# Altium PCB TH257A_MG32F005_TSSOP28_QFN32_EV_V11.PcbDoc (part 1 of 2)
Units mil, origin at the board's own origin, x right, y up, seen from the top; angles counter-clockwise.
Board outline 4094.49 x 2637.8 mil, 2 copper layers (Top Layer, Bottom Layer); 102 components, 87 nets, 480 pads, 216 vias.
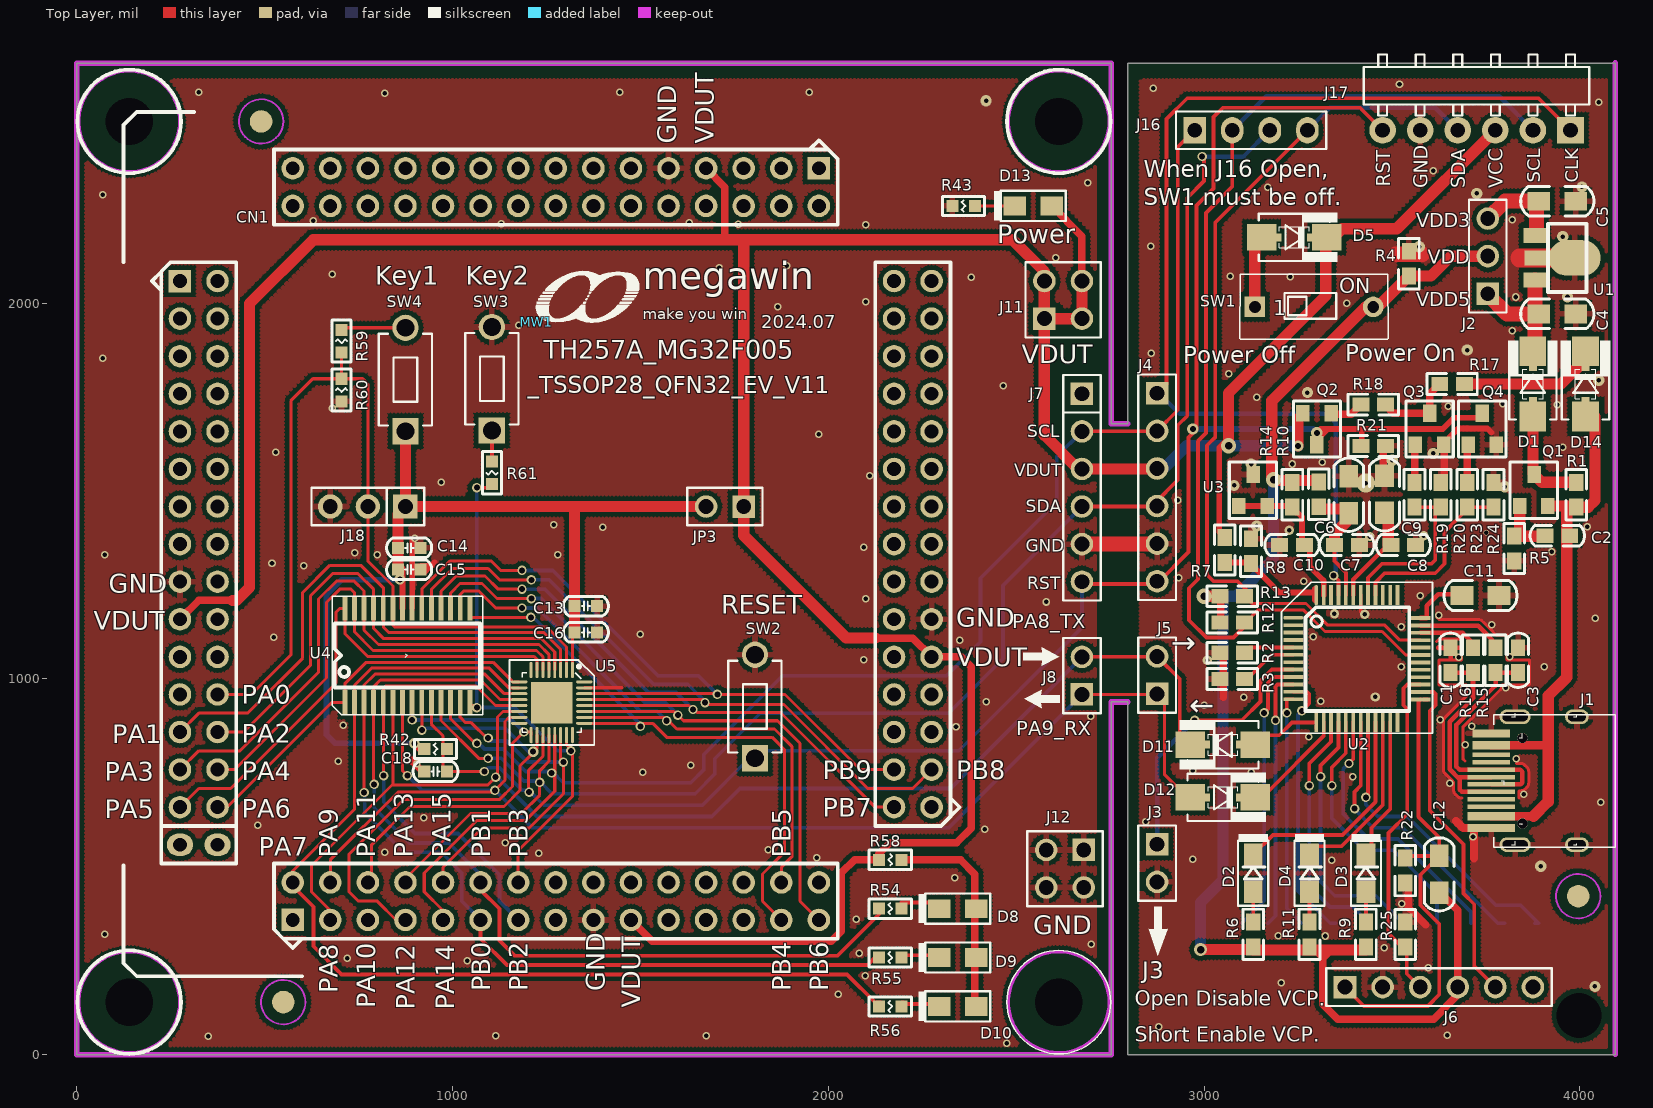
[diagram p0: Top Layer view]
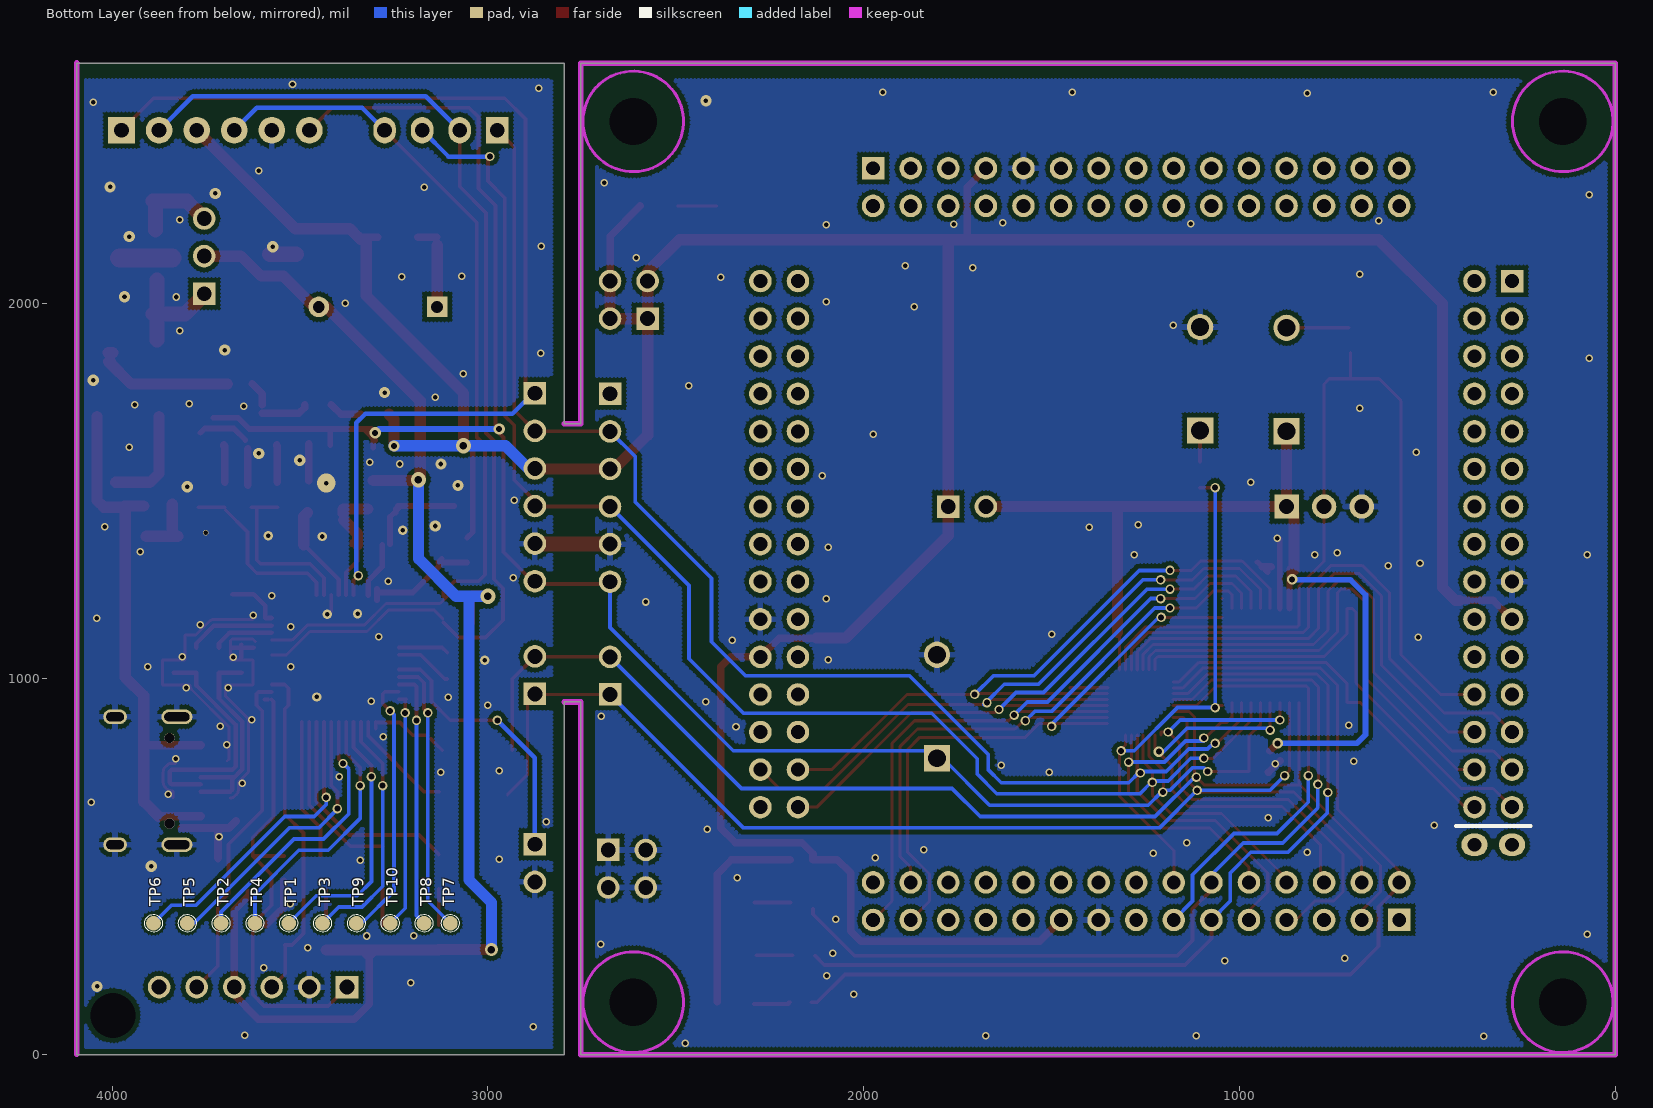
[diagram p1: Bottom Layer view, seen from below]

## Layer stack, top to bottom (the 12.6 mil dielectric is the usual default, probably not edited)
Top Layer: signal copper 1.4
Dielectric: dielectric 12.6, FR-4, Dk 4.8
Bottom Layer: signal copper 1.4

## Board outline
0,0 0,2637.8 2753.39,2637.8 2753.39,1678.74 2796.69,1678.74 2796.69,2637.8 4094.49,2637.8 4094.49,0 2796.69,0 2796.69,938.74 2753.39,938.74 2753.39,0

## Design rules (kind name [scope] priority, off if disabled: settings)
Clearance 12 [All] p1 off: gap=12
Clearance 7 [All] p2 off: gap=7
Clearance 6 [All] p3: gap=6
HoleSize 500-HoleSize [All] p1: absolutevalues=TRUE maxlimit=1500 minlimit=1 maxpercent=80.000 minpercent=20.000
PolygonConnect VIA [ISVIA] p1: connectstyle=Direct reliefconductorwidth=10 reliefentries=4 polygonreliefangle="90 Angle"
PolygonConnect "15 PolygonConnect" [All] p2: connectstyle=Relief reliefconductorwidth=15 reliefentries=4 polygonreliefangle="90 Angle"
RoomDefinition 3_MG32F005_QFN32 [InComponentClass('3_MG32F005_QFN32')] p1: confinementstyle=ConfineIn formatcopy=TRUE lockcomponents=FALSE outline 60.04,-466.26 4130,-466.26 4130,2953.74 60.04,2953.74
RoomDefinition 2_MG32F005_TSSOP28 [InComponentClass('2_MG32F005_TSSOP28')] p2: confinementstyle=ConfineIn formatcopy=TRUE lockcomponents=FALSE outline -190,-175 4240.04,-175 4240.04,2710 -190,2710
RoomDefinition 1_MLink_V13 [InComponentClass('1_MLink_V13')] p3: confinementstyle=ConfineIn formatcopy=TRUE lockcomponents=FALSE outline -110,-220 4180,-220 4180,2775 -110,2775
RoutingVias [All] p1: holewidth=16 width=25 viastyle="Through Hole" minholewidth=12 minwidth=25 maxholewidth=28 maxwidth=50
ShortCircuit [All] p1 off: allowed=FALSE
SilkscreenOverComponentPads [All] p1: minsilkscreentomaskgap=10
SolderMaskExpansion [All] p1: expansion=4
UnRoutedNet [All] p1 off:
Width [All] p1: maxlimit=100 minlimit=6 preferedwidth=8
24 further rules are at their usual default settings.

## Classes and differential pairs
component class 2_MG32F005_TSSOP28: C14 C15 C18 CN1 D8 D9 D10 D13 J7 J8 J11 J12 J18 JP3 R42 R43 R54 R55 R56 R58 R59 R60 R61 SW2 SW3 SW4 U4
component class 1_MLink_V13: C1 C2 C3 C4 C5 C6 C7 C8 C9 C10 C11 C12 D1 D2 D3 D4 D5 D11 D12 D14 J1 J2 J3 J4 J5 J6 J16 J17 MW1 Q1 Q2 Q3 Q4 R1 R2 R3 R4 R5 R6 R7 R8 R9 R10 R11 R12 R13 R14 R15 R16 R17 R18 R19 R20 R21 R22 R23 R24 R25 SW1 TP1 TP2 TP3 TP4 TP5 TP6 TP7 TP8 TP9 TP10 U1 U2 U3
component class 3_MG32F005_QFN32: C13 C16 U5

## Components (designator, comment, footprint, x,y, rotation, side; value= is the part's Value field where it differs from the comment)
C1 "15pF" 0603C 3655.59,1050 r270 top
C2 "0.1uF" 0603C 3940,1381.26 r0 top
C3 "15pF" 0603C 3835.59,1050 r270 top
C4 "4.7uF" 0805C 3940,1971.26 r0 top
C5 "4.7uF" 0805C 3940,2271.26 r0 top
C6 "4.7uF" 0805C 3385,1490 r90 top
C7 "0.1uF" 0603C 3380.04,1356.26 r0 top
C8 "0.1uF" 0603C 3530.04,1356.26 r0 top
C9 "4.7uF" 0805C 3480,1491.26 r90 top
C10 "0.1uF" 0603C 3234.09,1356.26 r0 top
C11 "4.7uF" 0805C 3735.59,1221.9 r0 top
C12 "4.7uF" 0805C 3625.59,480 r90 top
C13 "10uF" C-0603 1355.04,1193.74 r0 top
C14 "10uF" C-0603 885.04,1348.74 r180 top
C15 "0.1uF" C-0603 885.04,1290.74 r180 top
C16 "0.1uF" C-0603 1355.04,1123.74 r0 top
C18 "4.7uF" C-0603 955.04,753.74 r0 top
CN1 "QFP122-CKT" QFP122-P2.54-CKT 1275.04,1358.74 r0 top locked
D1 "1N5817" DIODE_SMA_SOD323 3875,1785 r90 top
D2 "Yellow" 0805D 3130.59,483.26 r90 top
D3 "Green" 0805D 3430.59,483.26 r90 top
D4 "Red" 0805D 3280.59,483.26 r90 top
D5 "1N5817" DIODE_SMA_SOD323 3240,2175 r0 top
D8 "Red" 0805D 2344.25,388.74 r180 top
D9 "Yellow" 0805D 2344.25,258.74 r180 top
D10 "Green" 0805D 2344.25,128.74 r180 top
D11 "1N5817" DIODE_SMA_SOD323 3050.04,825 r180 top
D12 "1N5817" DIODE_SMA_SOD323 3050.04,685 r0 top
D13 "Yellow" 0805D 2545.04,2258.74 r180 top
D14 "1N5817" DIODE_SMA_SOD323 4015,1785 r90 top
J1 "CJ-USB3-C16P" USB_CF_16_SMD 3799.28,729.12 r90 top
J2 "2&3 (0 ohm)" PS3P254#1 3755.04,2025 r90 top
J3 "VCP Option" PS2P254 2875.04,560 r270 top
J4 "OnBoard ICP/SWD Connector" PS6P254 2875.04,1760 r270 top
J5 "NC" PS2P254 2875.04,960 r90 top
J6 "CON6" PS6P254 3375.04,180 r0 top
J7 "CON6" PS6P254 2675.04,1758.74 r270 top locked
J8 "NC" PS2P254 2675.04,958.74 r90 top
J11 "CONN SOCKET 2x2/SM" PS2X2P254 2575.04,1958.74 r0 top
J12 "CONN SOCKET 2x2/SM" PS2X2P254 2680,545 r180 top
J16 "When J16 Open, SW1 must be off." PS4P254 2975.04,2460 r0 top
J17 "Off Board ICP/SWD Connector" PS6P254_90 3975.04,2460 r180 top
J18 "2&3 (0 ohm)" PS3P254#2 875.04,1458.74 r180 top
JP3 "JUMPER" PS2P254 1775.04,1458.74 r180 top
MW1 "MW-A4" MEGAWIN_3.4_1 1225.04,1948.74 r0 top
Q1 "IRLML6402" SOT23 3877.54,1501.97 r0 top
Q2 "2N3906" SOT23 3300.5,1665 r180 top
Q3 "3904" SOT23_132 3600.04,1665 r0 top
Q4 "3904" SOT23_132 3740.04,1665 r0 top
R1 "NC" 0603R 3990.04,1490 r270 top
R2 "0" 0603R 3075.04,1070 r0 top
R3 "NC" 0603R 3075.04,1000 r0 top
R4 "3.3K" 0603R 3545.04,2105 r270 top
R5 "1M" 0603R 3825.04,1347 r270 top
R6 "1K" 0603R 3130.59,320.26 r270 top
R7 "30K" 0603R 3055.04,1343 r90 top
R8 "10K" 0603R 3125.04,1340 r270 top
R9 "1K" 0603R 3430.59,320.26 r270 top
R10 "10" 0603R 3305,1491.26 r90 top
R11 "1K" 0603R 3280.59,320.26 r270 top
R12 "1.5K" 0603R 3075.04,1150 r180 top
R13 "1.5K" 0603R 3075.04,1220 r180 top
R14 "1K" 0603R 3235,1490 r270 top
R15 "30" 0603R 3775.59,1050 r90 top
R16 "30" 0603R 3715.59,1050 r90 top
R17 "4.7K" 0603R 3660,1785 r0 top
R18 "1K" 0603R 3450.04,1730 r0 top
R19 "4.7K" 0603R 3560.04,1490 r270 top
R20 "10K" 0603R 3630.04,1490 r270 top
R21 "1M" 0603R 3450.04,1620 r180 top
R22 "47K" 0603R 3535.59,490 r270 top
R23 "4.7K" 0603R 3700.04,1490 r270 top
R24 "10K" 0603R 3770.04,1490 r270 top
R25 "47K" 0603R 3535.59,320 r270 top
R42 "47K" R-0603 955.04,813.74 r0 top
R43 "1K" R-0603 2360.04,2258.74 r0 top
R54 "470" R-0603 2165.04,388.74 r0 top
R55 "470" R-0603 2165.04,258.74 r0 top
R56 "470" R-0603 2165.04,128.74 r0 top
R58 "0" R-0603 2165.04,518.74 r180 top
R59 "1K" R-0603 705.04,1898.74 r270 top
R60 "1M" R-0603 705.04,1768.74 r270 top
R61 "1K" R-0603 1105.04,1548.74 r90 top
SW1 "SW KEY-SPST" DIP2_SW 3135.08,1990 r0 top
SW2 "SW TACT-SPST" SW_T_2P 1805.04,926.54 r90 top
SW3 "Key2" SW_T_2P 1105.04,1798.74 r90 top
SW4 "Key1" SW_T_2P 875.04,1796.54 r90 top
TP1 "T POINT A" PIN1_1H0 3530.04,350 r90 bottom
TP2 "T POINT A" PIN1_1H0 3710.04,350 r90 bottom
TP3 "T POINT A" PIN1_1H0 3440.04,350 r180 bottom
TP4 "T POINT A" PIN1_1H0 3620.04,350 r180 bottom
TP5 "T POINT A" PIN1_1H0 3800.04,350 r180 bottom
TP6 "T POINT A" PIN1_1H0 3890.04,350 r180 bottom
TP7 "T POINT A" PIN1_1H0 3100.04,350 r180 bottom
TP8 "T POINT A" PIN1_1H0 3170.04,350 r180 bottom
TP9 "T POINT A" PIN1_1H0 3350.04,350 r180 bottom
TP10 "T POINT A" PIN1_1H0 3260.04,350 r90 bottom
U1 "AIC1734-33(SOT-89)" SOT89 3880,2120.31 r270 top
U2 "MG84FG516_LQFP48" LQFP48_7X7_050 3406.51,1054.39 r270 top
U3 "TL431A" SOT23 3130,1501.97 r0 top
U4 "MG32F005_TSSOP28_170P0.65" TSSOP28_170P065 880.04,1062.5 r0 top
U5 "MG32F005_QFN32_4X4P0.4" QFN32_4X4P040 1264.41,937.13 r270 top

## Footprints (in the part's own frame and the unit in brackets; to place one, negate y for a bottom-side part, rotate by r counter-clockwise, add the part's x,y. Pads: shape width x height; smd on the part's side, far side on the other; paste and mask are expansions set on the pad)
0603C [mil]
  rect 45x38 smd: 1(33,0) 2(-33,0)
  silkscreen extent -72,-28 72,28
0603R [mil]
  rect 45x38 smd: 1(33,0) 2(-33,0)
  silkscreen extent -67,-28 67,28
0805C [mil]
  rect 60x50 smd: 1(-49.21,0) 2(49.21,0)
  silkscreen extent -97,-39 97,39
0805D [mil]
  rect 60x50 smd: 1(-49.21,0) 2(49.21,0)
  silkscreen extent -87,-40 104,40
C-0603 [mil]
  rect 32x32 smd: 1(-30,0) 2(30,0)
  silkscreen extent -60,-26 60,26
DIODE_SMA_SOD323 [mm]
  rect 2x1.8 smd: 1(-2.2,0) 2(2.2,0)
  rect 0.95x0.54 smd: 1(-1.35,0) 2(1.35,0)
  silkscreen extent -2.4,-1.68 2.92,1.68
DIP2_SW [mm]
  rect 1.4x1.4 hole 0.8: 1(0,0)
  round 1.4 hole 0.8: 2(8,0)
  silkscreen extent -1.02,-2.2 9.02,2.2
LQFP48_7X7_050 [mm]
  oval 0.254x1.35 smd: 1(-2.75,-4.292)
  rect 0.254x1.35 smd: 2(-2.25,-4.292) 3(-1.75,-4.292) 4(-1.25,-4.292) 5(-0.75,-4.292) 6(-0.25,-4.292) 7(0.25,-4.292) 8(0.75,-4.292) 9(1.25,-4.292) 10(1.75,-4.292) 11(2.25,-4.292) 12(2.75,-4.292) 25(2.763,4.292) 26(2.263,4.292) 27(1.763,4.292) 28(1.263,4.292) 29(0.763,4.292) 30(0.263,4.292) 31(-0.237,4.292) 32(-0.737,4.292) 33(-1.237,4.292) 34(-1.737,4.292) 35(-2.237,4.292) 36(-2.737,4.292)
  rect 1.35x0.254 smd: 13(4.286,-2.744) 14(4.286,-2.244) 15(4.286,-1.744) 16(4.286,-1.244) 17(4.286,-0.744) 18(4.286,-0.244) 19(4.286,0.256) 20(4.286,0.756) 21(4.286,1.256) 22(4.286,1.756) 23(4.286,2.256) 24(4.286,2.756) 37(-4.286,2.756) 38(-4.286,2.256) 39(-4.286,1.756) 40(-4.286,1.256) 41(-4.286,0.756) 42(-4.286,0.256) 43(-4.286,-0.244) 44(-4.286,-0.744) 45(-4.286,-1.244) 46(-4.286,-1.744) 47(-4.286,-2.244)
  oval 1.35x0.254 smd: 48(-4.286,-2.744)
  silkscreen extent -5.15,-5.09 5.05,5.11
MEGAWIN_3.4_1 [mil]
  silkscreen extent -2,0 272,135
PIN1_1H0 [mm]
  round 1 smd: 1(0,0)
  silkscreen extent -0.6,-0.6 0.6,0.6
PS2P254 [mil]
  rect 60x60 hole 39.37: 1(0,0)
  round 60 hole 39.37: 2(100,0)
  silkscreen extent -50,-50 150,50
PS2X2P254 [mil]
  rect 60x60 hole 39.37: 1(0,0)
  round 60 hole 39.37: 2(0,100) 3(100,0) 4(100,100)
  silkscreen extent -50,-50 150,150
PS3P254#1 [mil]
  rect 60x60 hole 39.37: 1(0,0)
  round 60 hole 39.37: 2(100,0) 3(200,0)
  silkscreen extent -50,-50 250,50
PS3P254#2 [mil]
  rect 65x65 hole 39.37: 1(0,0)
  round 65 hole 39.37: 2(100,0) 3(200,0)
  silkscreen extent -50,-50 250,50
PS4P254 [mil]
  rect 60x70 hole 39.37: 1(0,0)
  oval 60x70 hole 39.37: 2(100,0) 3(200,0) 4(300,0)
  silkscreen extent -50,-50 350,50
PS6P254 [mil]
  rect 60x60 hole 39.37: 1(0,0)
  round 60 hole 39.37: 2(100,0) 3(200,0) 4(300,0) 5(400,0) 6(500,0)
  silkscreen extent -50,-50 550,50
PS6P254_90 [mm]
  rect 1.8x1.8 hole 1: 1(0,0)
  round 1.8 hole 1: 2(2.54,0) 3(5.08,0) 4(7.62,0) 5(10.16,0) 6(12.7,0)
  silkscreen extent -1.27,-5.11 13.97,-1
QFN32_4X4P040 [mm]
  oval 1.1x0.2 smd: 1(-2.2,1.4) 2(-2.2,1) 3(-2.2,0.6) 4(-2.2,0.2) 5(-2.2,-0.2) 6(-2.2,-0.6) 7(-2.2,-1) 8(-2.2,-1.4) 17(2.2,-1.4) 18(2.2,-1) 19(2.2,-0.6) 20(2.2,-0.2) 21(2.2,0.2) 22(2.2,0.6) 23(2.2,1) 24(2.2,1.4)
  oval 0.2x1.1 smd: 9(-1.4,-2.2) 10(-1,-2.2) 11(-0.6,-2.2) 12(-0.2,-2.2) 13(0.2,-2.2) 14(0.6,-2.2) 15(1,-2.2) 16(1.4,-2.2) 25(1.4,2.2) 26(1,2.2) 27(0.6,2.2) 28(0.2,2.2) 29(-0.2,2.2) 30(-0.6,2.2) 31(-1,2.2) 32(-1.4,2.2)
  rect 2.8x2.8 smd: 33(0,0)
  silkscreen extent -2.87,-2.87 2.87,2.87
QFP122-P2.54-CKT [mil]
  rect 60x60 hole 37: 1(-700,-1000) 61(700,1000) 91(-1000,700)
  round 60 hole 37: 2(-700,-900) 3(-600,-1000) 4(-600,-900) 5(-500,-1000) 6(-500,-900) 7(-400,-1000) 8(-400,-900) 9(-300,-1000) 10(-300,-900) 11(-200,-1000) 12(-200,-900) 13(-100,-1000) 14(-100,-900) 15(0,-1000) 16(0,-900) 17(100,-1000) 18(100,-900) 19(200,-1000) 20(200,-900) 21(300,-1000) 22(300,-900) 23(400,-1000) 24(400,-900) 25(500,-1000) 26(500,-900) 27(600,-1000) 28(600,-900) 29(700,-1000) 30(700,-900) 31(1000,-700) 32(900,-700) 33(1000,-600) 34(900,-600) 35(1000,-500) 36(900,-500) 37(1000,-400) 38(900,-400) 39(1000,-300) 40(900,-300) 41(1000,-200) 42(900,-200) 43(1000,-100) 44(900,-100) 45(1000,0) 46(900,0) 47(1000,100) 48(900,100) 49(1000,200) 50(900,200) 51(1000,300) 52(900,300) 53(1000,400) 54(900,400) 55(1000,500) 56(900,500) 57(1000,600) 58(900,600) 59(1000,700) 60(900,700) 62(700,900) 63(600,1000) 64(600,900) 65(500,1000) 66(500,900) 67(400,1000) 68(400,900) 69(300,1000) 70(300,900) 71(200,1000) 72(200,900) 73(100,1000) 74(100,900) 75(0,1000) 76(0,900) 77(-100,1000) 78(-100,900) 79(-200,1000) 80(-200,900) 81(-300,1000) 82(-300,900) 83(-400,1000) 84(-400,900) 85(-500,1000) 86(-500,900) 87(-600,1000) 88(-600,900) 89(-700,1000) 90(-700,900) 92(-900,700) 93(-1000,600) 94(-900,600) 95(-1000,500) 96(-900,500) 97(-1000,400) 98(-900,400) 99(-1000,300) 100(-900,300) 101(-1000,200) 102(-900,200) 103(-1000,100) 104(-900,100) 105(-1000,0) 106(-900,0) 107(-1000,-100) 108(-900,-100) 109(-1000,-200) 110(-900,-200) 111(-1000,-300) 112(-900,-300) 113(-1000,-400) 114(-900,-400) 115(-1000,-500) 116(-900,-500) 117(-1000,-600) 118(-900,-600) 119(-1000,-700) 120(-900,-700)
  oval 70x60 hole 37: 121(-1000,-800) 122(-900,-800)
  silkscreen extent -1150,-1150 1075,1150
R-0603 [mil]
  rect 32x32 smd: 1(-30,0) 2(30,0)
  silkscreen extent -56,-26 56,26
SOT23 [mil]
  rect 36x43.31 smd: 1(-37.5,-41.97) 2(37.5,-41.97)
  rect 36x46.06 smd: 3(0.5,41.97)
  silkscreen extent -63,-74 63,75
SOT23_132 [mil]
  rect 36x43.31 smd: 1(-37.5,-41.97) 3(37.5,-41.97)
  rect 36x46.06 smd: 2(0.5,41.97)
  silkscreen extent -63,-74 63,75
SOT89 [mm]
  rect 1.016x1.5 smd: 1(-1.5,0) 3(1.5,0)
  oval 2.4x3.5 smd: 2(0,2.7)
  rect 1.016x2.6 smd: 2(0,0.6)
  silkscreen extent -2.3,0.9 2.3,3.5
SW_T_2P [mil]
  rect 70x70 hole 47.24: 1(-137.79,0)
  round 70 hole 47.24: 2(137.79,0)
  silkscreen extent -122,-71 122,71
TSSOP28_170P065 [mil]
  rect 13x65 smd: 1(-166.34,-125) 2(-140.75,-125) 3(-115.16,-125) 4(-89.57,-125) 5(-63.98,-125) 6(-38.39,-125) 7(-12.8,-125) 8(12.8,-125) 9(38.39,-125) 10(63.98,-125) 11(89.57,-125) 12(115.16,-125) 13(140.75,-125) 14(166.34,-125) 15(166.34,125) 16(140.75,125) 17(115.16,125) 18(89.57,125) 19(63.98,125) 20(38.39,125) 21(12.8,125) 22(-12.8,125) 23(-38.39,125) 24(-63.98,125) 25(-89.57,125) 26(-115.16,125) 27(-140.75,125) 28(-166.34,125)
  silkscreen extent -200,-158 201,158
USB_CF_16_SMD [mm]
  rect 0.55x3.2 smd: A1(-3.2,0.9) A4(-2.4,0.9)
  rect 0.3x3.2 smd: A5(-1.25,0.9) A6(-0.25,0.9) A7(0.25,0.9) B6(0.75,0.9) B7(-0.75,0.9) B8(-1.75,0.9)
  rect 0.3x2.54 smd: A8(1.25,0.9) B5(1.75,0.9)
  rect 0.55x2.54 smd: A9(2.4,0.9) A12(3.2,0.9)
  oval 1x2.1 hole 0.6 slot 1.7 at 90 deg: M1(-4.32,-0.718) M2(4.32,-0.718)
  oval 1x1.6 hole 0.6 slot 1.2 at 90 deg: M3(4.32,-4.898) M4(-4.32,-4.898)
  round 0.7 hole 0.7 unplated: M5(-2.89,-1.218) M6(2.89,-1.218)
  silkscreen extent -4.48,-7.5 4.55,0.74

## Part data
C1 C3 C7 C12 C13 C14 C15 C16 C18: library part "CAP NP_Dup1"
C2 C8 C10: library part "CAP NP"
C4 C5: library part "C NP"
C6 C9 C11: library part CAP
D1 D5 D11 D12 D14: library part "DIODE SCHOTTKY"
D2 D3 D4: library part Led0_0
D8 D9 D10 D13: library part LED
J1: "TPYE-C-9"
J2 J18: library part CON3
J3 J5 J8: library part CON2
J4 J17: library part CON6
J7: library part CON6_Dup1
J16: library part CON4
MW1: library part MW_A4_2
Q1: library part "MOSFET P GSD"
Q2: library part 2N3906_0
Q3 Q4: library part "NPN BCE"
R1 R2 R3 R4 R43 R54 R55 R56 R58: library part R_Dup4
R5 R6 R7 R8 R9 R11 R12 R13 R17 R18 R19 R22 R23 R25: library part R_Dup2
R10 R14 R15 R16: library part R_Dup5
R20 R21 R24: library part R_Dup1
R42 R59 R60 R61: library part R_Dup3
SW3 SW4: library part "SW TACT-SPST"
U1: library part AIC1722-33
U3: library part TL431/CYL
U4: library part MG32F005_TSSOP28
U5: library part MG32F005_QFN32

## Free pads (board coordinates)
  round 120 hole 125.98 unplated: 0(140,140) 0(140,2483.43) 0(2613.39,140) 0(2613.39,2483.43)
  round 60 smd mask+39.37: 0(491,2483.43) 0(550,140) 0(3995.59,421.9)
  round 100 hole 120 unplated: 0(3997.8,104.65)

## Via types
v1: diameter 20, hole 12, Top Layer to Bottom Layer, tented both sides, 135 vias
v2: diameter 25, hole 16, Top Layer to Bottom Layer, tented both sides, 45 vias
v3: diameter 30, hole 12, Top Layer to Bottom Layer, tented both sides, 17 vias
v4: diameter 25, hole 12, Top Layer to Bottom Layer, tented both sides, 7 vias
v5: diameter 28, hole 16, Top Layer to Bottom Layer, tented both sides, 3 vias
v6: diameter 40, hole 20, Top Layer to Bottom Layer, tented both sides, 3 vias
v7: diameter 30, hole 16, Top Layer to Bottom Layer, tented both sides, 3 vias
v8: diameter 50, hole 12, Top Layer to Bottom Layer, tented both sides, 1 vias
v9: diameter 35, hole 20, Top Layer to Bottom Layer, tented both sides, 1 vias
v10: diameter 15, hole 12, Top Layer to Bottom Layer, tented both sides, 1 vias

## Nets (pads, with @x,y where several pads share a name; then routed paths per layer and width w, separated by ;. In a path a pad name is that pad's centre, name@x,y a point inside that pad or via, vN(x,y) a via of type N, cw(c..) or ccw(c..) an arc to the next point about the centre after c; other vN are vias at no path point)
2.495V: C10.1 R14.1 U2.47 U3.1 U3.2 | length 416.4
  Top Layer w15: U3.1@3090,1460 U3.1@3092.5,1460 U3.2@3167.5,1460 3235,1460 R14.1@3240,1460 ; R14.1@3235.59,1456 R14.1@3245.59,1446 ; R14.1@3245.59,1442 R14.1@3245.59,1446 ; R14.1@3245.59,1452 R14.1@3245.59,1446 ; C10.1@3260.59,1359 3260.59,1431 R14.1@3245.59,1446 ; C10.1@3281.59,1357 3281.59,1356.26 3281.59,1298.45 3318.18,1261.86 U2.47@3318.18,1223.13
516P24: TP7.1 U2.9 | length 742.8
  Top Layer w10: v2(3160.04,910) 3170.04,920 3170.04,990 3185.22,1005.18 U2.9@3237.52,1005.18
  Bottom Layer w10: TP7.1@3100.04,350 3160.04,410 v2(3160.04,910)
516P25: TP8.1 U2.10 | length 688
  Top Layer w10: v2(3190.04,890) 3190.04,980 3195.53,985.49 U2.10@3237.52,985.49
  Bottom Layer w10: TP8.1@3170.04,350 3190.04,370 v2(3190.04,890)
516P26: TP9.1 U2.11 | length 717
  Top Layer w10: U2.11@3237.52,965.81 3274.23,965.81 3280.04,960 3280.04,935 v2(3260.04,915)
  Bottom Layer w10: v2(3260.04,915) 3250.04,905 3250.04,435.95 3335.99,350 TP9.1@3350.04,350
516P27: TP10.1 U2.12 | length 634.3
  Top Layer w10: v2(3220.04,910) 3220.04,943.23 3217.15,946.12 U2.12@3237.52,946.12
  Bottom Layer w10: v2(3220.04,910) 3220.04,390 TP10.1@3260.04,350
516P32: TP3.1 U2.15 | length 662
  Top Layer w10: v2@3280.04,715 v2(3280.04,716.26) 3280.04,775 3337.86,832.82 U2.15@3337.86,885.65
  Bottom Layer w10: v2@3280.04,715 3280.04,448.38 3335.42,393 3397.04,393 TP3.1@3440.04,350
516P33: TP1.1 U2.16 | length 710.4
  Top Layer w10: v2(3310.04,740) 3310.04,770 3357.55,817.51 U2.16@3357.55,885.65
  Bottom Layer w10: v2(3310.04,740) 3310.04,460.8 3347.84,423 3457.04,423 TP1.1@3530.04,350
516P34: TP4.1 U2.17 | length 713.1
  Top Layer w10: v2@3340.04,715 v2(3340.04,716.26) 3340.04,765 3377.23,802.19 U2.17@3377.23,885.65
  Bottom Layer w10: v2@3340.04,715 3340.04,628.7 3424.74,544 3503.31,544 3620.04,427.27 TP4.1@3620.04,350
516P35: TP2.1 U2.18 | length 733.6
  Top Layer w10: v2@3385.32,775.28 3396.92,786.88 U2.18@3396.92,885.65
  Bottom Layer w10: v2@3385.32,775.28 3370.04,760 3370.04,641.12 3437.16,574 3515.74,574 3710.04,379.7 TP2.1@3710.04,350
  other v2: 3385.59,775
516P36: TP5.1 U2.19 | length 774.1
  Top Layer w10: v2@3400.04,655 3400.04,699.45 3416.6,716.01 U2.19@3416.6,885.65
  Bottom Layer w10: v2@3400.04,655 3400.04,653.55 3449.59,604 3528.16,604 3782.16,350 TP5.1@3800.04,350 TP5.1@3790.59,350
  other v2: 3400.59,655
516P37: TP6.1 U2.20 | length 822.9
  Top Layer w10: v2@3430.04,685 v2(3430.59,685) 3436.29,690.7 U2.20@3436.29,885.65
  Bottom Layer w10: v2@3430.04,685 3430.04,665.98 3462.02,634 3540.59,634 3776.59,398 3842.04,398 TP6.1@3890.04,350 TP6.1@3880.59,350
CHIP_VDD: C13.1 C14.2 C15.2 C16.1 J18.1 JP3.2 R42.1 SW4.1 U4.22 U5.1 | length 2585
  Top Layer w9: U5.1@1319.53,1023.74 C16.1@1319.53,1123.74
  Top Layer w15: U4.22@867.24,1187.5 867.24,1264.74 867.24,1290.74 C15.2@867.24,1293.74
  Top Layer w20: v5(899.04,828.74) R42.1@919.04,808.74
  Top Layer w30: C15.2@855.04,1290.74 C14.2@855.04,1348.74 ; C14.2@855.04,1360.74 C14.2@855.04,1348.74 ; SW4.1@875.04,1658.74 J18.1@875.04,1458.74 ; C16.1@1325.04,1123.74 C13.1@1325.04,1193.74 1325.04,1458.74 ; JP3.2@1675.04,1458.74 1325.04,1458.74 ; C14.2@855.04,1348.74 855.04,1438.74 J18.1@875.04,1458.74 ; J18.1@875.04,1458.74 1325.04,1458.74
  Bottom Layer w15: v5@860.04,1263.74 705.04,1263.74 665.04,1223.74 665.04,851.64 687.94,828.74 v5(899.04,828.74)
  other v5: 860.04,1264.74
D+: C3.1 J1.A6 J1.B6 R15.2 | length 648.6
  Top Layer w12: J1.A6@3763.84,719.27 3842.37,719.27 3847.09,724 3847.09,753 3841.45,758.64 J1.B6@3763.84,758.64 3679.95,758.64 3671.59,767 3671.59,878.54 3775.59,982.54 R15.2@3775.59,1017 C3.1@3835.59,1017
D-: C1.1 J1.A7 J1.B7 R16.2 | length 590.1
  Top Layer w12: C1.1@3655.59,1017 R16.2@3715.59,1017 3715.59,948 3653.59,886 3653.59,759.54 3679.75,733.39 ; 3675.59,738.96 3685.99,738.96 ; 3680.59,734.23 3680.59,705.23 3686.23,699.59 J1.B7@3763.84,699.59 ; 3680.94,733.9 3685.99,738.96 ; J1.A7@3763.84,738.96 3685.99,738.96
DET_VDUT: R7.2 R8.1 U2.48 | length 318.6
  Top Layer w15: R7.2@3055.04,1310 3125.04,1310 R8.1@3132.6,1310 ; R8.1@3122.6,1320 R8.1@3130.32,1312.28 ; R8.1@3122.8,1307.24 3124.04,1306 3200.04,1230 3290.98,1230 ; U2.48@3295.04,1210 3295.04,1223.13 U2.48@3295.04,1240
DUT_CLK: J4.1 J17.1 U2.45 | length 2846.4
  Top Layer w10: J4.1@2875.04,1760 2900.04,1785 2900.04,2490 2955.04,2545 3890.04,2545 J17.1@3975.04,2460 ; v2(3344.92,1275) 3357.55,1262.37 U2.45@3357.55,1223.13
  Bottom Layer w12: J4.1@2875.04,1760 2880.04,1760 2935.04,1705 3326.26,1705 3350,1681.26 3350,1280.08 v2(3344.92,1275)
DUT_RST: C18.2 J4.6 J7.6 J17.6 Q2.3 Q4.2 R21.1 R42.2 SW2.1 U4.10 U5.19 | length 5318
  Top Layer w8: U4.10@944.02,937.5 944.02,879.76 975.04,848.74 975.04,813.74 975.04,753.74 C18.2@985.04,753.74 v2(1085.04,753.74) ; v2@1203.04,701.74 1203.04,756.74 1240.79,794.49 U5.19@1240.79,850.51
  Top Layer w10: J7.6@2676.04,1252.74 J4.6@2875.04,1252.74 ; J4.6@2878.04,1257 2958.79,1337.75 2958.79,1642.75 2975.54,1659.5 2980.04,1664 2980.04,1665 2980.04,2260 3025.04,2305 3025.04,2495 3050.04,2520 3415.04,2520 J17.6@3475.04,2460
  Top Layer w15: Q2.3@3300,1635 Q2.3@3305,1640 ; v7(3300,1655) 3310,1665 3330,1665 ; Q2.3@3305,1615 3305,1623.03 Q2.3@3305,1640 ; v7@3305,1658 3305,1655 Q2.3@3305,1640 ; R21.1@3420,1622 3420,1665 ; Q4.2@3730.63,1695 3665,1695 3635,1665 3420,1665 ; Q2.3@3305,1640 3310,1645 3330,1665 ; 3330,1665 3420,1665
  Bottom Layer w10: v2(1085.04,753.74) 1095.04,763.74 1125.04,763.74 1184.89,703.89 1204.04,703.89 1205.04,703.89 v2@1206.11,702.82 ; v2@1205.04,701.74 1206.04,700.74 1243.04,663.74 1665.04,663.74 1790.04,788.74 SW2.1@1805.04,788.74 1825.04,808.74 2347.04,808.74 2675.04,1136.74 J7.6@2675.04,1258.74
  Bottom Layer w15: v7(2970.04,1665) 3290,1665 v7(3300,1655)
  other v2: 1204.04,698.74
FAIL: D4.2 U2.22 | length 461.4
  Top Layer w10: D4.2@3280.59,555 3365.88,555 3475.66,664.78 U2.22@3475.66,885.65
GND_POWER: C1.2 C3.2 C4.2 C5.2 C6.2 C7.1 C8.1 C9.2 C10.2 C11.2 C13.2 C14.1 C15.1 C16.2 C18.1 CN1.17 CN1.41 CN1.69 CN1.107 J1.A1 J1.A12 J1.M1 J1.M2 J1.M3 J1.M4 J3.2 J4.5 J6.2 J7.5 J12.1 J12.2 J12.3 J12.4 J17.5 J18.3 Q3.3 Q4.3 R2.2 R3.2 R4.2 R5.1 R8.2 R20.2 R21.2 R22.1 R24.2 R25.2 R43.1 R60.2 SW2.2 SW3.2 U1.2 U2.42 U3.3 U4.21 U5.31 | length 3393.3
  Top Layer w8: 3619.08,1099.79 3625.08,1105.79 3655.59,1105.79 3680.76,1105.79 3685.59,1100.96 3685.59,1058 3685.59,1050.5 3677.59,1050.5 3625.59,1050.5 3625.59,983.5 3690.59,983.5 3698.59,983.5 3698.59,977 3698.59,955.04 3641.57,898.02 ; v1@3619.59,1164 3625.12,1158.47 3729.12,1158.47 ; 3641.57,747.52 cw(c3653.59,759.54) 3636.59,759.54 ; 3641.59,898 ccw(c3653.61,885.98) 3636.61,885.98 3636.59,759.54 ; 3674.21,687.57 ccw(c3686.23,699.59) 3686.23,682.59 cw(c3686.23,699.59) 3674.19,687.59 3668.59,693.19 ; 3694.59,781.64 3688.59,787.64 3688.59,825 3688.59,871.5 3787.59,970.5 ccw(c3775.59,982.54) 3792.59,982.54 cw(c3775.59,982.54) 3787.61,970.52 ; 3792.59,983.5 3802.59,983.5 3865.59,983.5 3865.59,1050.5 3813.59,1050.5 3805.59,1050.5 3805.59,1059 3805.59,1116.5 3778.13,1116.5 3758.11,1136.52 3741.16,1153.47 ; 3831.13,775.64 3841.45,775.64 ; 3837.83,682.68 3837.83,693 3837.83,702.27 3842.37,702.27 ; 3854.39,707.25 cw(c3842.37,719.27) 3842.37,702.27 ; 3859.12,711.98 ccw(c3847.09,724) 3864.09,724 ; 3859.12,765.02 cw(c3847.09,753) 3864.09,753 ; 3636.59,759.54 ccw(c3653.59,759.54) 3641.59,747.5 3660.34,728.75 3663.59,725.5 3663.59,722 3663.59,705.23 ; 3663.59,705.23 ccw(c3680.59,705.23) 3668.59,693.19 ; 3663.59,705.23 ccw(c3680.59,705.23) 3668.57,693.21 ; 3729.12,1158.47 cw(c3729.12,1141.47) 3741.14,1153.49 ; 3729.12,1158.47 cw(c3729.12,1141.47) 3741.16,1153.47 ; 3841.45,775.64 cw(c3841.45,758.64) 3853.47,770.66 ; 3841.45,775.64 cw(c3841.45,758.64) 3853.49,770.64 ; 3842.37,702.27 ccw(c3842.37,719.27) 3854.41,707.27 3859.1,711.96 ccw(c3847.09,724) 3864.09,724 ; 3853.49,770.64 3859.1,765.04 cw(c3847.09,753) 3864.09,753 ; 3864.09,724 3864.09,753
  Top Layer w9: U5.31@1351.02,976.5 1451.02,976.5
  Top Layer w10: 3416.6,1179.01 U2.42@3416.6,1223.13
  Top Layer w12: 3623.59,1083 C1.2@3655.59,1083 C1.2@3656.59,1083 ; 3656.59,1054 C1.2@3656.59,1083 ; C1.2@3656.59,1091 C1.2@3656.59,1083 ; 3683.59,1083 C1.2@3656.59,1083
  Top Layer w15: U4.21@892.83,1187.5 892.83,1290.74 892.83,1348.74 v1@892.83,1373.44 ; C15.1@925.04,1283.74 940.04,1298.74 952.24,1310.94 ; Q3.3@3645.29,1635.29 3676.24,1666.24 3753.7,1666.24 3764.94,1655
  Top Layer w20: 891.94,782.84 903.04,771.74 C18.1@923.04,751.74 ; C15.1@915.45,1298.74 940.04,1298.74 ; 3051.04,951.9 3051.04,1000 R2.2@3051.04,1067.53 ; C9.2@3477.04,1528 3477.04,1540.47 3477.04,1582 3477.04,1620 R21.2@3477.04,1625.53 ; R22.1@3543.59,461 3543.59,457 3543.59,401.9 3543.59,391.89 3559.03,376.44 3590.08,345.4 ; R20.2@3639.04,1515 3639.04,1523 Q3.3@3639.04,1612.53
  Top Layer w22: 3670.59,621.9 3689.38,603.12 J1.A1@3763.84,603.12 J1.A1@3815.59,603.12 ; 3718.47,522.79 3718.47,580 J1.A1@3718.47,597.25
  Top Layer w40: J7.5@2675.04,1358.74 J4.5@2875.04,1358.74 ; 3509.94,2130 3545.04,2130 3572.6,2130 3581.04,2130
  Top Layer w50: 3840,2120.31 U1.2@3903.62,2120.31 U1.2@3980,2120.31
  other v1: 2475.04,30.64 349.94,48.74 1115.04,50.64 1675.04,50.64 3647.59,51.9 2879.94,75 2026.04,160.64 3205.59,191.9 2098.04,210.64 3596.59,231.9 1039.94,250.74 719.94,256.74 2083.04,270.64 3479.94,285 2699.94,293.74 3322.59,316 3197.59,317 75.04,320.64 2074.04,360.64 3526.59,401.9 2336.04,470.64 3339.94,518 2969.94,520 1969.94,524.74 1229.94,536.74 819.94,538.74 1839.94,545.74 1139.94,563.74 3715.59,580 2416.04,600.64 482.04,610.64 2845.04,620 924.04,630.64 4055.59,671.9 3850.59,693 3653.59,722 3395.59,740 1507.04,751.74 3125.04,751.9 2969.94,756 1634.04,770.64 905.04,773.74 696.04,780.64 3830.59,788 3695.59,825 3278.04,846 2339.94,872.74 3712.59,874 709.94,876.74 3628.59,891.9 2698.04,900.64 2999.94,930 2419.94,939.74 3309.94,940 3105,951.9 3802.59,976 3690.59,977 3525.04,1031.9 3905.59,1031.9 2094.04,1050.64 3677.59,1058 3813.59,1059 2349.94,1102.74 524.04,1110.64 3290.04,1111.9 1499.94,1118.74 3524.59,1139 3765.59,1144 4040.59,1161.9 3624.59,1170 2579.94,1204.74 2099.94,1213.74 3575.04,1221.9 3265.04,1260 2932,1269.26 605.04,1300.64 519.94,1307.74 75.04,1330.64 800.04,1330.64 1280.04,1330.64 739.94,1335.74 3924.59,1339 2095.04,1350.64 899.94,1373.74 1399.94,1403.74 4019.94,1405 1270.04,1410.64 2929.94,1475 969.94,1523.74 2110.04,1540.64 3235,1571.9 3315,1576.26 529.94,1603.74 3955,1616.26 1975.04,1650.64 679.94,1720 3649.94,1725 3939.94,1730 3795,1731.9 3139.94,1750 2465.04,1780.64 3065.04,1811.9 69.94,1853.74 2859.94,1866 3820,1926.26 1176.04,1940.64 1865.04,1990.64 3379.94,2000 2099.94,2003.74 3829.94,2016.26 2379.94,2068.74 3229.94,2070 3070.04,2071.9 679.94,2076.74 1709.94,2094.74 1889.94,2099.74 2605.04,2120.64 2857.59,2151.9 2099.94,2208.74 1760,2210 1130.04,2210.64 1629.94,2213.74 629.94,2218.74 3820,2221.9 69.94,2288.74 3169.94,2308 2690.04,2320.64 3610.04,2351.9 4049.94,2535 819.94,2558.74 325.04,2560.64 1445.04,2560.64 1950.04,2560.64 2865,2571.9 3520,2581.9
  other v3: 4040.04,181.9 3895.59,501.9 3140,1406.93 3800,1511.26 3079.94,1515 3125.04,1571.9 3500.59,1582 3609.94,1600 3275,1761.9 4049.94,1795 3700,1875 3967.04,2016.9 3572.6,2150 3954.59,2177 3725.59,2291.9 4005.59,2309 2419.94,2538.74
  other v4: 3455.59,952 3008.11,1050 3427.04,1172 3347.04,1173 3440.59,1379 3585,1381.26 3226.59,1396
  other v8: 3430,1521.26
  other v10: 3750.59,1389
ICP/SWD_SCL: J16.2 J17.2 R12.2 U2.31 | length 2959.9
  Top Layer w8: R12.2@3120.04,1160 3144.04,1184 3264,1184 3322,1126 3474,1126 3513.9,1086.1 ; 3513.94,1086.1 3536.31,1063.73 U2.31@3575.5,1063.73
  Top Layer w10: J16.2@3075.04,2485 J16.2@3075.04,2460 3075.04,2310 3005.04,2240 3005.04,1654 2983.79,1632.75 2983.79,1265.05 2960,1241.26 2960,1156.26 3006.26,1110 3078.04,1110 3113.04,1145 R12.2@3118.04,1150
  Bottom Layer w12: J16.2@3075.04,2460 3165.04,2550 3785.04,2550 J17.2@3875.04,2460
ICP/SWD_SDA: J16.4 J17.4 R13.2 U2.33 | length 2399.4
  Top Layer w8: R13.2@3108.04,1220 3127.04,1201 3271.04,1201 3329.04,1143 3481.04,1143 3520.94,1103.1 U2.33@3575.5,1103.1
  Top Layer w10: R13.2@3118.04,1220 3118.04,1231 3089.04,1260 3025.04,1260 3007.79,1277.25 3007.79,1621.75 3030.04,1644 3030.04,2215 J16.4@3275.04,2460
  Bottom Layer w12: J16.4@3275.04,2460 3335.04,2520 3615.04,2520 J17.4@3675.04,2460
